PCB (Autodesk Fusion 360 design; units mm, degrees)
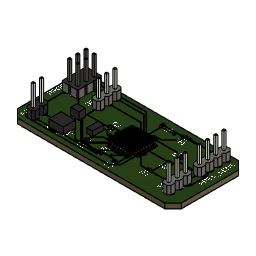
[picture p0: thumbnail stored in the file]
sketch "Outline" plane through (0, 0, 0) normal (0, 0, 1) x axis (1, 0, 0)
  line L1 (2.54, 0) -> (0, 2.54)
  line L2 (48.26, 0) -> (2.54, 0)
  line L3 (50.8, 2.54) -> (48.26, 0)
  line L4 (50.8, 20.32) -> (50.8, 2.54)
  line L5 (48.26, 22.86) -> (50.8, 20.32)
  line L6 (2.54, 22.86) -> (48.26, 22.86)
  line L7 (0, 20.32) -> (2.54, 22.86)
  line L8 (0, 2.54) -> (0, 20.32)
canvas "Canvas1" bodies "Board"
canvas "Canvas2" bodies "Board"
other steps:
base_feature "Base Feature1"
base_feature "Base Feature1"
base_feature "Base Feature1"
base_feature "Base Feature1"
extrude "Extrude1" sketch "Outline" blind 1.5 bodies "Board"
pcbextrude "PCBExtrude1"
pcbextrude "PCBExtrude1"
pcbextrude "PCBExtrude1"
pcbextrude "PCBExtrude1"
base_feature "Base Feature1"
base_feature "Base Feature1"
base_feature "Base Feature1"
box_primitive "BoxPrimitive1" DistanceX 3.5 DistanceY 1.8 DistanceZ 1.4857 OffsetDistanceX 0 OffsetDistanceY 0
box_primitive "BoxPrimitive1" DistanceX 2 DistanceY 2.55 DistanceZ 2.2281 OffsetDistanceX 0 OffsetDistanceY 0
box_primitive "BoxPrimitive1" DistanceX 4.4224 DistanceY 3.7846 DistanceZ 2.16 OffsetDistanceX 0 OffsetDistanceY 0
pcbextrude "PCBExtrude1"
pcbextrude "PCBExtrude2" bodies "CopperHoles"
create_component "CreateComponent1"
create_component "CreateComponent2"
create_component "CreateComponent3"
create_component "CreateComponent4"
create_component "CreateComponent5"
create_component "CreateComponent6"
create_component "CreateComponent1"
create_component "CreateComponent6"
create_component "CreateComponent7"
create_component "CreateComponent8"
create_component "CreateComponent9"
create_component "CreateComponent10"
as_built_joint "As-built1"
create_component "CreateComponent14"
create_component "CreateComponent15"
create_component "CreateComponent16"
create_component "CreateComponent17"
named bodies: "Board", "CopperHoles"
